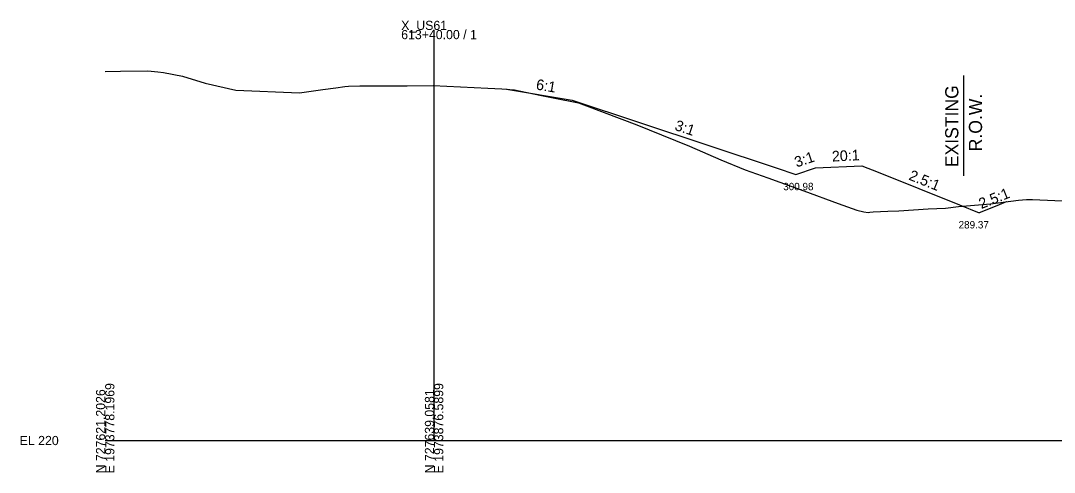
# Model space of a CAD drawing. Extents: x -26 to 1604, y -13 to 9623.
# Drawn here: x -25.7 to 288.6, y 3490.3 to 3627.8 of the extents above; entities that cross this region are included whole.
import ezdxf

# ---------------------------------------------------------------- set-up
doc = ezdxf.new("R2010")
doc.units = 0
for name, color, linetype in [('Draft_XS_Grid', 7, 'Continuous'), ('DTM_X_GROUND', 7, 'Continuous'), ('SLOPE_STAKES_FILL', 7, 'Continuous'), ('XS_CELL', 7, 'Continuous'), ('XS_P_GROUND', 7, 'Continuous'), ('XS_P_TX_DCH', 7, 'Continuous'), ('XS_P_TX_FS_BS', 7, 'Continuous'), ('XS_X_ROW', 7, 'Continuous')]:
    doc.layers.add(name, color=color, linetype=linetype)

msp = doc.modelspace()

# ---------------------------------------------------------------- linework, layer by layer
at = {"layer": 'DTM_X_GROUND'}
msp.add_lwpolyline([(0, 3612.33), (4.65, 3612.41), (12.93, 3612.54), (15.98, 3612.23), (17.75, 3612.05), (23.52, 3610.96), (30.38, 3608.81), (39.68, 3606.63), (59.05, 3605.91), (66.22, 3606.83), (70.13, 3607.42), (72.89, 3607.83), (73.99, 3607.88), (77.38, 3608.03), (91.81, 3608.03), (99.71, 3608.05), (116.38, 3607.28), (120.62, 3607.08), (122.2, 3606.96), (123.01, 3606.9), (124.46, 3606.78), (132.14, 3605.2), (136.22, 3604.37), (143.91, 3602.8), (146.29, 3601.89), (161.6, 3596.08), (169.18, 3593.04), (177.65, 3589.65), (187.2, 3585.43), (194.59, 3582.37), (201.49, 3580.03), (212.44, 3576.01), (222.84, 3572.13), (228.5, 3570.13), (230.64, 3569.67), (231.94, 3569.45), (232.52, 3569.5), (233.52, 3569.61), (237.92, 3569.85), (241.33, 3569.94), (250.23, 3570.5), (255.44, 3570.74), (259.46, 3571.3), (269.2, 3572.04), (277.72, 3573.17), (280.14, 3573.37), (281.95, 3573.43), (293.24, 3572.85)], dxfattribs=at)
at = {"layer": 'XS_CELL'}
for p, q in [((100, 3500), (100, 3625)), ((0, 3500), (100, 3500)), ((100, 3500), (600, 3500))]:
    msp.add_line(p, q, dxfattribs=at)
at = {"layer": 'XS_P_GROUND'}
for points in [[(122, 3606.98), (142, 3603.64)], [(142, 3603.64), (204, 3582.98), (210, 3580.98), (216, 3582.98), (230, 3583.68), (235, 3581.68)], [(235, 3581.68), (259.76, 3571.77), (265.76, 3569.37)], [(273.99, 3572.67), (273.92, 3572.64), (271.76, 3571.77), (271.61, 3571.71), (265.76, 3569.37)]]:
    msp.add_lwpolyline(points, dxfattribs=at)
at = {"layer": 'XS_X_ROW'}
msp.add_line((261, 3611.16), (261, 3580.62), dxfattribs=at)

# ---------------------------------------------------------------- texts
at = {"layer": 'Draft_XS_Grid'}
msp.add_text('-', height=0.0001, dxfattribs=at).set_placement((0, 3500))
at = {"layer": 'SLOPE_STAKES_FILL'}
for p in [(141.96, 3603.58), (203.96, 3582.92), (215.96, 3582.92), (229.96, 3583.62), (209.96, 3580.92), (259.72, 3571.71), (271.72, 3571.71), (273.96, 3572.61), (265.72, 3569.31)]:
    msp.add_text('X', height=0.12, dxfattribs=at).set_placement(p)
at = {"layer": 'XS_CELL'}
for s, p in [('X_US61', (90, 3625)), ('613+40.00 / 1', (90, 3622.2)), ('EL 220', (-26, 3498.6))]:
    msp.add_text(s, height=2.8, dxfattribs=at).set_placement(p)
for s, p in [('E 1973778.1969', (2.8, 3490)), ('E 1973876.5899', (102.8, 3490)), ('N 727621.2026', (0, 3490)), ('N 727639.0581', (100, 3490))]:
    msp.add_text(s, height=2.8, rotation=90, dxfattribs=at).set_placement(p)
at = {"layer": 'XS_P_GROUND'}
for p in [(121.96, 3606.92), (234.96, 3581.62)]:
    msp.add_text('X', height=0.12, dxfattribs=at).set_placement(p)
at = {"layer": 'XS_P_TX_DCH'}
for s, p in [('300.98', (206.15, 3576.21)), ('289.37', (259.47, 3564.57))]:
    msp.add_text(s, height=2.25, dxfattribs=at).set_placement(p)
at = {"layer": 'XS_P_TX_FS_BS'}
for s, rotation, p in [('6:1', 350.5377, (130.83, 3606.9)), ('3:1', 341.5651, (172.93, 3594.62)), ('3:1', 18.4349, (210.21, 3583.12)), ('20:1', 2.8624, (221.03, 3584.92)), ('2.5:1', 338.1986, (244.08, 3579.5)), ('2.5:1', 21.8014, (266.38, 3570.45))]:
    msp.add_text(s, height=3.24, rotation=rotation, dxfattribs=at).set_placement(p)
at = {"layer": 'XS_X_ROW'}
for s, p in [('EXISTING', (259.4, 3583.22)), ('R.O.W.', (266.6, 3588.06))]:
    msp.add_text(s, height=4, rotation=90, dxfattribs=at).set_placement(p)

doc.saveas('drawing.dxf')
